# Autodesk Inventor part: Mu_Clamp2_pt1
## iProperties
Shininess: 64.0
Length Units: 11272
Angle Units: 11279
Time Units: 11290
Mass Units: 11286
Length Display Precision: 3
Angle Display Precision: 2
Compacted: True
Part Number: Mu_Clamp2_pt1
Document SubType Name: Modeling
Created: 2004-08
Designer: John Blackburn
Material: Aluminum-6061
Manufacturer: Standard
Standards Organization: Custom
Density: 0.0
Volumn: 0.0
Area: 0.0
PropertySet Name: Model Information
Control State: 0
Master: False
Checked Out: False
Author: John Blackburn
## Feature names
1. Extrusion1
2. Split1
